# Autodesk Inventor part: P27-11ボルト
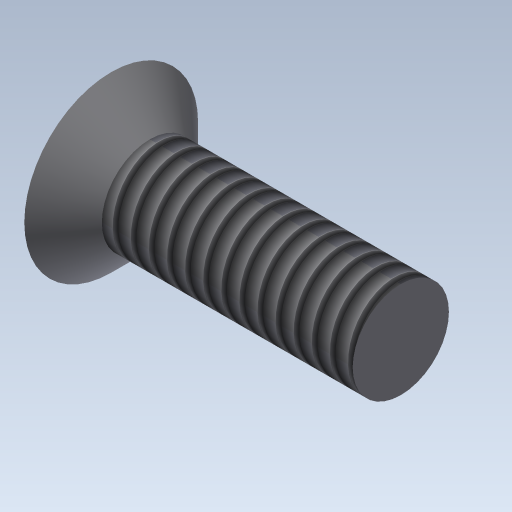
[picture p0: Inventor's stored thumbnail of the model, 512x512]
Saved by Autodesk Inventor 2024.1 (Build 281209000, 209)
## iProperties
Shininess: 64.0
Length Units: 11269
Angle Units: 11279
Time Units: 11290
Mass Units: 11284
Length Display Precision: 2
Angle Display Precision: 1
Created: 2002-10
Part Number: P27-11ボルト
Document SubType Name: ﾓﾃﾞﾘﾝｸﾞ
Designer: 株式会社富士システム
Stock Number: P24-11ボルト
Density: 1 g/cm^3
Material: 一般
Appearance: 既定
Density: 0.0
Volumn: 0.0
Area: 0.0
PropertySet Name: Model Information
Control State: 0
Master: False
Checked Out: False
Author: 株式会社富士システム
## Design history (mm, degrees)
sketch "ｽｹｯﾁ1"
  geometry: L1 (0, 0)-(0, -6); L2 (0, -6)-(2.677, -3.324); L3 (2.677, -3.324)-(20, -3.323); L4 (20, -3.323)-(20, 0); L5 (20, 0)-(0, 0); 1 further point
  constraints: 10 end point, 2 perpendicular, 1 coincident, 1 parallel, 1 vertical
  dimensions: "d14" = 45 deg angle of L5 L2; "d15" = 12 diameter of L1.end L5; "d16" = 20 distance between parallel lines of L4 L1; "d17" = 6.647 diameter of L3 L5
revolve "回転1" sketch "ｽｹｯﾁ1" stored, may be unused: angle "d5" = 90 deg
feature "ねじ1" dims "d6" = 10, "d7" = 0
sketch "ｽｹｯﾁ2"
  geometry: L1 (0, -6)-(0, 6); L2 (-6, 0)-(6, 0); L3 (-5.999, 0.718)-(-5.957, 0.718); L4 (-5.999, -0.718)-(-5.957, -0.718); L5 (5.957, -0.718)-(5.999, -0.718); L6 (5.957, 0.718)-(5.999, 0.718); L7 (0.718, -5.999)-(0.718, -5.957); L8 (-0.718, -5.999)-(-0.718, -5.957); L9 (-0.7, -3.938)-(-0.7, -0.7); L10 (0.7, -3.938)-(0.7, -0.7); L11 (0.7, 0.7)-(0.7, 3.938); L12 (0.718, 5.957)-(0.718, 5.999); L13 (-0.7, 0.7)-(-0.7, 3.938); L14 (-0.718, 5.957)-(-0.718, 5.999); L15 (-3.938, 0.7)-(-0.7, 0.7); L16 (0.7, 0.7)-(3.938, 0.7); L17 (-3.938, -0.7)-(-0.7, -0.7); L18 (0.7, -0.7)-(3.938, -0.7); A1 r 4 centre (0, 0) between (0.7, 3.938) and (-0.7, 3.938); A2 r 4 centre (0, 0) between (3.938, -0.7) and (3.938, 0.7); A3 r 4 centre (0, 0) between (-3.938, 0.7) and (-3.938, -0.7); A4 r 4 centre (0, 0) between (-0.7, -3.938) and (0.7, -3.938); 1 further point
  constraints: 36 end point, 8 point on circle, 4 centre point, 2 midpoint, 1 coincident, 1 perpendicular, 1 vertical, 13 other
extrude "押し出し1" cut sketch "ｽｹｯﾁ2" distance "d12" = 1; taper "d13" = 0 deg
node "ソリッド1"
node "ソリッド ボディ"
node "サーフェス ボディ"
other parameters: "d8" = 0.7, "d9" = 0.7 (= d8), "d10" = 0.7 (= d8), "d11" = 0.7 (= d8)
